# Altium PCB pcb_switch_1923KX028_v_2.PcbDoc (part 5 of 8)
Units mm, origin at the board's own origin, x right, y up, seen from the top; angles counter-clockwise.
Board outline 297.2 x 112.05 mm, 6 copper layers (Component Side, GND Layer 1, Inner Layer 1, Inner Layer 2, GND Layer 2, Solder Side), stack 1.578 mm thick; 545 components, 377 nets, 3174 pads, 1537 vias.
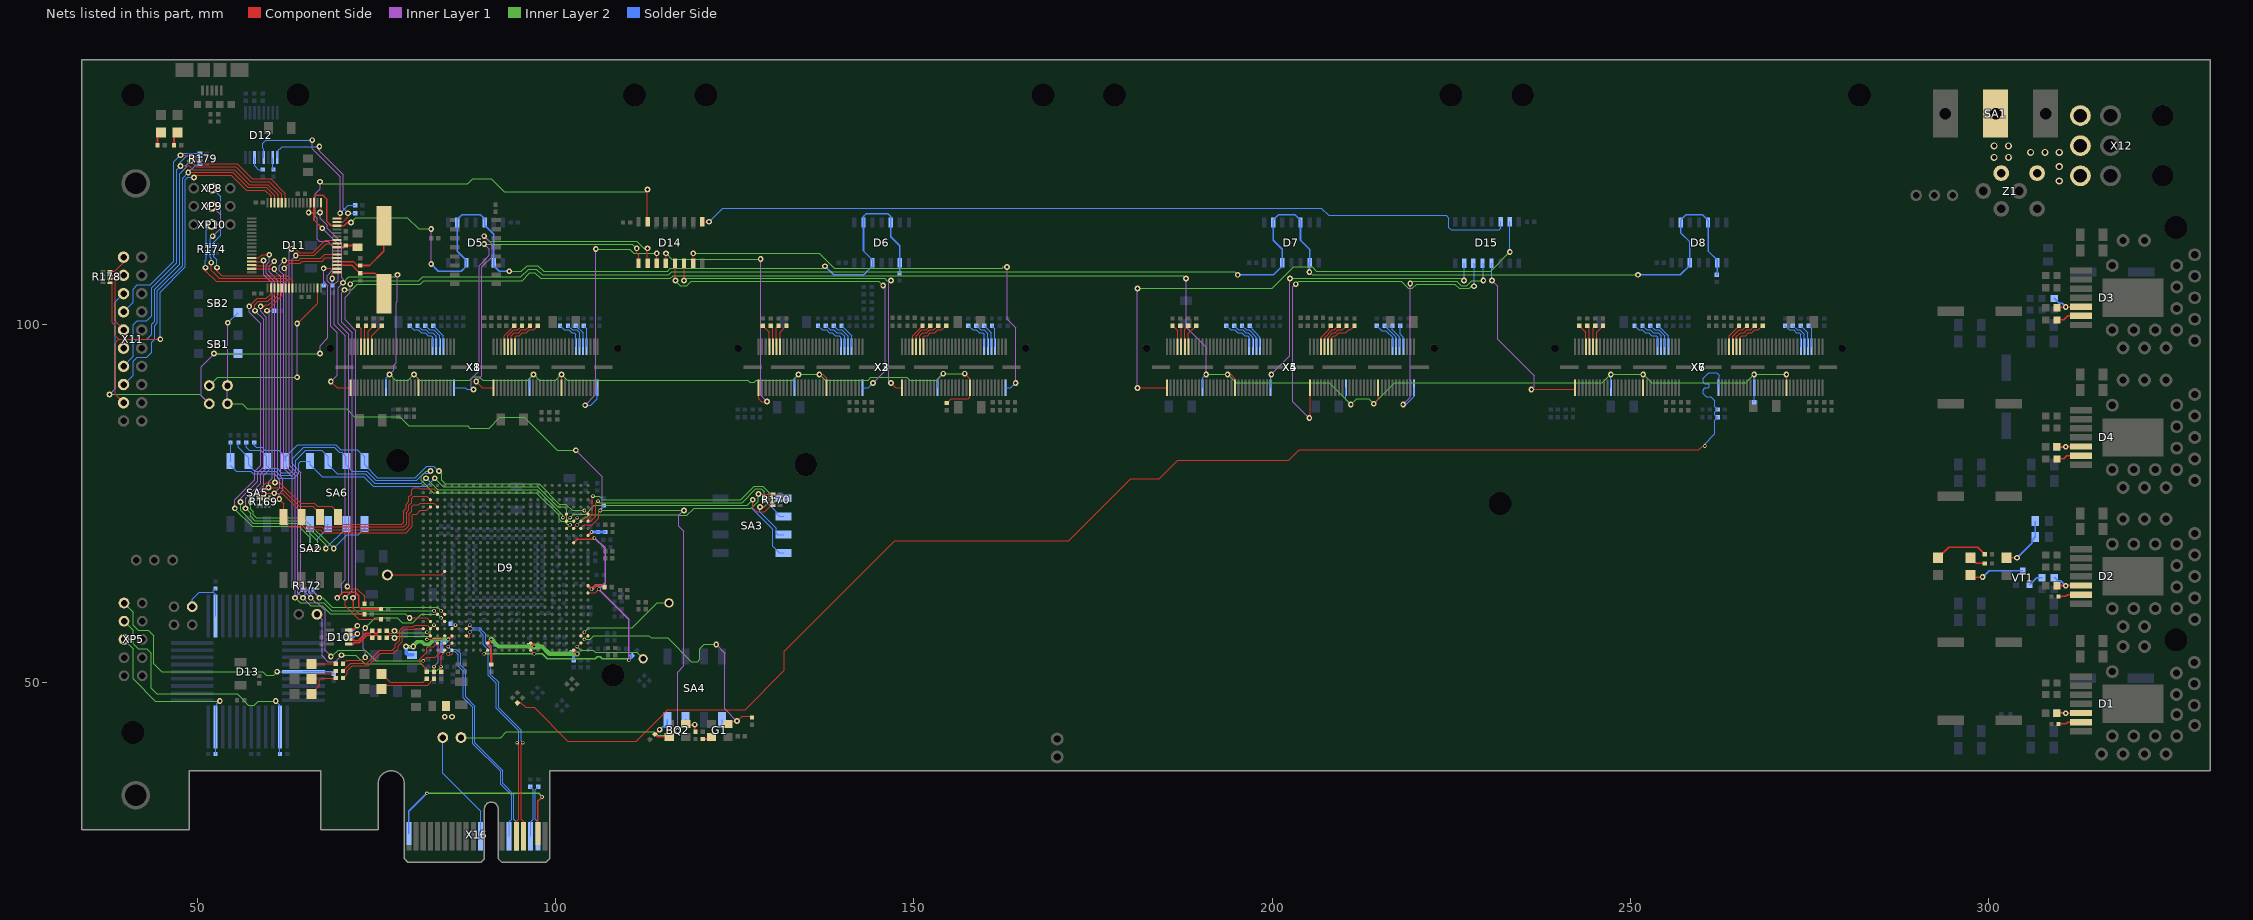
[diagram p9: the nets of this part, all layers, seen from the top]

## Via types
v1: diameter 0.8, hole 0.4, Component Side to Solder Side, tented both sides, 884 vias
v2: diameter 0.5, hole 0.3, Component Side to Solder Side, tented both sides, 269 vias
v3: diameter 1, hole 0.6, Component Side to Solder Side, tented both sides, 95 vias
v4: diameter 0.5/0.5/0.3/0.3/0.5/0.5 (per signal layer), hole 0.3, Component Side to Solder Side, tented both sides, 80 vias
v5: diameter 0.5/0.3/0.3/0.5/0.3/0.5 (per signal layer), hole 0.3, Component Side to Solder Side, tented both sides, 37 vias
v6: diameter 0.5/0.3/0.3/0.3/0.3/0.5 (per signal layer), hole 0.3, Component Side to Solder Side, tented both sides, 34 vias
v7: diameter 0.5/0.5/0.5/0.3/0.5/0.5 (per signal layer), hole 0.3, Component Side to Solder Side, tented both sides, 29 vias
v8: diameter 0.5, hole 0.3, Component Side to Solder Side, 25 vias
v9: diameter 0.5/0.3/0.5/0.3/0.3/0.5 (per signal layer), hole 0.3, Component Side to Solder Side, tented both sides, 25 vias
v10: diameter 0.5/0.5/0.3/0.5/0.5/0.5 (per signal layer), hole 0.3, Component Side to Solder Side, tented both sides, 19 vias
v11: diameter 0.6, hole 0.3, Component Side to Solder Side, tented both sides, 14 vias
v12: diameter 0.8, hole 0.5, Component Side to Solder Side, tented both sides, 11 vias
v13: diameter 0.5/0.3/0.5/0.5/0.3/0.5 (per signal layer), hole 0.3, Component Side to Solder Side, tented both sides, 7 vias
v14: diameter 0.8, hole 0.4, Component Side to Solder Side, 5 vias
v15: diameter 0.5/0.5/0.5/0.5/0.5/0.5 (per signal layer), hole 0.3, Component Side to Solder Side, tented both sides, 2 vias
v16: diameter 0.8, hole 0.5, Component Side to Solder Side, 1 vias

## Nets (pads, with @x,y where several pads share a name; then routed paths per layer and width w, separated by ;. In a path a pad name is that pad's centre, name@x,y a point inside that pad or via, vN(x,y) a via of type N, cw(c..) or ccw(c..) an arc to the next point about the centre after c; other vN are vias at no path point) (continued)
M_SGMII_L3DATI_3_P: C90.1 R93.2 R97.1 X7.59 | length 203.9
  Component Side w0.15: C90.1@94.654,47.146 95.134,47.146 95.781,46.5 96.962,46.5 101.672,41.79 111.228,41.79 115.638,46.2 126.438,46.2 131.91,51.672 131.91,54.372 147.338,69.8 171.638,69.8 180.238,78.4 184.238,78.4 186.838,81 202.338,81 203.819,82.481 259.6,82.481 260.119,83 v8(260.4,83)
  Solder Side w0.15: v8(260.4,83) 260.4,83.281 261.805,84.686 261.805,86.605 R97.1@262.2,87 261.805,87.395 261.805,87.705 R93.2@262.2,88.1 261.805,88.495 261.805,89.333 261.228,89.91 260.59,89.91 260.21,90.29 260.21,90.8 cw(c260.51,90.8) 260.51,91.1 260.732,91.1 ccw(c260.732,91.4) 261.032,91.4 ccw(c260.732,91.4) 260.732,91.7 260.51,91.7 cw(c260.51,92) 260.21,92 260.21,92.472 260.938,93.2 262.11,93.2 262.41,92.9 262.41,92.455 262.315,92.36 X7.59@262.315,91.135
MCU_A_3.3V: C118.2 D11.24 L4.2 | length 3.1
  Component Side w0.3: D11.24@69.45,110.75 70.45,110.75 C118.2@70.7,111 72.05,111 L4.2@72.3,110.75
MCU_FS: D11.4 SA6.6 | length 52.5
  Component Side w0.15: v1(58.8,102.5) 59.3,102.5 59.5,102.7 59.9,102.7 61.25,104.05 D11.4@61.25,105.05
  Inner Layer 1 w0.15: v1(56.7,74.3) 56.7,75.7 58.8,77.8 58.8,79.1 59.6,79.9 59.6,101 58.8,101.8 v1(58.8,102.5)
  Inner Layer 2 w0.15: v1(56.7,74.3) 57.4,73.6 57.4,73.2 58,72.6 64.5,72.6 67.9,69.2 v1(67.9,68.7)
  Solder Side w0.15: v1(67.9,68.7) 70.8,71.6 70.8,72 70.77,72.03 SA6.6@70.77,72.1
MCU_MISO: D11.5 R175.2 SA6.5 | length 54.2
  Component Side w0.15: v1(59.7,101.9) 61.75,103.95 D11.5@61.75,105.05
  Inner Layer 1 w0.15: v1(57.4,75.2) 57.4,75.7 59.2,77.5 59.2,78.9 60,79.7 60,101.6 v1(59.7,101.9)
  Inner Layer 2 w0.15: v1(57.4,75.2) 57.4,74.2 57.8,73.8 57.8,73.4 58.2,73 64.7,73 v1(69,68.7)
  Solder Side w0.15: v1(59.7,101.9) R175.2@60.7,101.9 ; v1(69,68.7) 70.9,70.6 72.4,70.6 73.4,71.6 73.4,72 73.31,72.09 SA6.5@73.31,72.1
MCU_MOSI: D11.2 SA6.8 | length 52.1
  Component Side w0.15: v1(57.2,102.5) 58.3,103.6 59.6,103.6 60.25,104.25 D11.2@60.25,105.05
  Inner Layer 1 w0.15: v1(55.2,74.3) 55.2,75.5 58,78.3 58,79.5 58.8,80.3 58.8,100.1 57.2,101.7 v1(57.2,102.5)
  Inner Layer 2 w0.15: v1(55.2,74.3) 55.2,74.2 57.6,71.8 64.1,71.8 65.7,70.2 v1(65.7,68.7)
  Solder Side w0.15: SA6.8@65.69,72.1 65.7,72.09 v1(65.7,68.7)
MCU_SCK: D11.3 SA6.7 | length 52.4
  Component Side w0.15: v1@57.9,101.9 58,102 58,102.7 58.5,103.2 59.8,103.2 60.75,104.15 D11.3@60.75,105.05
  Inner Layer 1 w0.15: v1(56,75.2) 56,75.7 58.4,78.1 58.4,79.3 59.2,80.1 59.2,100.7 v1(58,101.9)
  Inner Layer 2 w0.15: v1(56,75.2) 56,74 57.8,72.2 64.3,72.2 66.8,69.7 v1(66.8,68.7)
  Solder Side w0.15: v1(66.8,68.7) 66.8,70.1 68.2,71.5 68.2,72.1 SA6.7@68.23,72.1
MDC_1: D5.2 D5.5 D5.9 D5.12 D6.2 D6.5 D6.9 D6.12 D11.30 D11.35 R94.2 R225.2 | length 192.3
  Component Side w0.22: v1(67.4,113.4) 66.25,114.55 D11.35@66.25,116.95 66.25,117.75 66.5,118 67.5,118 68,117.5 68,114.4 68.65,113.75 D11.30@69.45,113.75 70.45,113.75 70.9,114.2 v1(71.4,114.2) ; v1(69.5,61.8) 70.3,62.6 72,62.6 72.5,62.1 72.5,60.6 72.85,60.25 R225.2@75.6,60.25
  Inner Layer 1 w0.17: v1(67.4,113.4) 69.6,111.2 69.6,106.1 69.1,105.6 69.1,99.9 70.6,98.4 70.6,64.3 70.1,63.8 70.1,62.4 v1(69.5,61.8) ; v1(82.6,108.4) v1(82.6,113.3)
  Inner Layer 2 w0.17: v1(71.4,114.2) 72.1,114.9 79.3,114.9 80.9,113.3 v1(82.6,113.3) ; v1(93.5,107.4) 95.2,107.4 96,108.2 97.5,108.2 98.3,107.4 115.6,107.4 116,107.8 137.3,107.8 v1(137.6,108.1)
  Solder Side w0.22: v1(82.6,108.4) 83.6,107.4 86.8,107.4 87.53,108.13 D5.5@87.53,108.6 87.53,108.97 87.5,108.94 86.26,110.18 D5.9@86.26,114.2 86.26,114.66 86.9,115.3 89.5,115.3 90.07,114.73 D5.12@90.07,114.2 90.07,113.83 91.34,112.56 D5.2@91.34,108.6 91.34,108.16 92.1,107.4 v1(93.5,107.4) ; v1(137.6,108.1) 138.8,106.9 143,106.9 144.23,108.13 D6.12@144.23,108.6 144.23,108.97 142.96,110.24 D6.2@142.96,114.2 142.96,115.06 143.3,115.4 146.4,115.4 146.77,115.03 D6.5@146.77,114.2 146.77,112.23 148.04,110.96 D6.9@148.04,108.6 148.04,107.14 R94.2@148,107.1
MDC_2: D7.2 D7.5 D7.9 D7.12 D8.2 D8.5 D8.9 D8.12 R95.2 R226.2 | length 272.9
  Component Side w0.22: v1(71.7,61.8) 71.7,60.4 72.6,59.5 R226.2@73.3,59.5
  Inner Layer 1 w0.17: v1(71.3,105.6) 71.3,104.5 70.6,103.8 70.6,100.6 72.1,99.1 72.1,62.2 v1(71.7,61.8)
  Inner Layer 2 w0.17: v1(71.3,105.6) 71.8,106.1 80.9,106.1 81.4,106.6 95.1,106.6 96.2,107.7 97.3,107.7 98.1,106.9 115.8,106.9 116.2,107.3 194.8,107.3 v1(195.2,106.9) ; v1(205.2,107.3) 205.6,106.9 v1(251.1,106.9)
  Solder Side w0.22: v1(195.2,106.9) 200.2,106.9 201.43,108.13 D7.12@201.43,108.6 201.43,110.47 200.16,111.74 D7.2@200.16,114.2 200.16,114.56 200.9,115.3 203.2,115.3 203.97,114.53 D7.5@203.97,114.2 203.97,111.73 205.24,110.46 D7.9@205.24,108.6 205.2,108.56 v1(205.2,107.3) ; v1(251.1,106.9) 257,106.9 258.33,108.23 D8.12@258.33,108.6 258.33,111.47 257.06,112.74 D8.2@257.06,114.2 257.06,114.56 257.8,115.3 260.1,115.3 260.87,114.53 D8.5@260.87,114.2 260.87,110.23 262.14,108.96 D8.9@262.14,108.6 262.14,106.94 R95.2@262.1,106.9
MDIO_1: D11.33 D11.36 R100.2 R111.2 X1.39 X1.99 X2.39 X2.99 X3.39 X3.99 X8.39 X8.99 | length 192.4
  Component Side w0.15: v1(65.5,115.6) 65.75,115.85 D11.36@65.75,116.95 ; v1(67.1,115.6) 67.25,115.75 D11.33@67.25,116.95 ; v1(70.9,63.4) 71.2,63.1 72.2,63.1 73.3,62 R111.2@73.3,61 ; v1(80.2,93) 80.815,92.385 X1.39@80.815,91.135 ; v1(100.8,93) 100.82,92.98 X1.99@100.82,91.135 ; v1(136.8,93) 137.3,93 137.815,92.485 X2.39@137.815,91.135 ; R100.2@154.6,89 155.2,89.6 157.6,89.6 157.82,89.82 X2.99@157.82,91.135 157.82,92.38 v1(157.1,93.1)
  Inner Layer 1 w0.15: v1(67.1,115.6) 67.1,114.8 68.1,113.8 68.1,113.4 70.1,111.4 70.1,106.5 70.3,106.3 v1(70.3,105.8) 69.6,105.1 69.6,100.1 71.1,98.6 71.1,63.6 v1(70.9,63.4) ; v1(76.8,93) 77.4,93.6 77.4,94.3 77.7,94.6 77.7,103 77.9,103.2 v1(77.9,106.9)
  Inner Layer 2 w0.15: v1(65.5,115.6) v1(67.1,115.6) ; v1(70.3,105.8) 71.1,106.6 77.6,106.6 v1(77.9,106.9) ; v1(76.8,93) 77.6,92.2 79.4,92.2 v1(80.2,93) 81,92.2 88,92.2 88.5,92.7 89.3,92.7 89.8,92.2 96.1,92.2 v1(96.9,93) 97.7,92.2 100,92.2 v1(100.8,93) 101.6,92.2 126.8,92.2 127.1,91.9 127.7,91.9 128,92.2 133.1,92.2 v1(133.9,93) v1(136.8,93) 137.6,92.2 143.6,92.2 144,92.6 149,92.6 149.4,92.2 153.2,92.2 v1(154.1,93.1) v1(157.1,93.1)
  Solder Side w0.15: X8.99@76.31,91.135 76.31,92.51 v1(76.8,93) ; X8.39@96.315,91.135 96.315,92.415 v1(96.9,93) ; X3.99@133.31,91.135 133.31,92.41 v1(133.9,93) ; X3.39@153.315,91.135 153.315,92.415 154,93.1 v1(154.1,93.1)
MDIO_2: R104.2 R227.2 X4.39 X4.99 X5.39 X5.99 X6.39 X6.99 X7.39 X7.99 | length 290.1
  Component Side w0.15: v1(70.6,61.8) 70.6,60.7 72.5,58.8 R227.2@75.6,58.8 ; v1(193.8,93) 194.2,93 194.815,92.385 X4.39@194.815,91.135 ; v1(214.2,88.9) 214.82,89.52 X4.99@214.82,91.135 ; v1(251.8,93) 251.815,92.985 X6.39@251.815,91.135 ; v1(271.8,93) 271.82,92.98 X6.99@271.82,91.135
  Inner Layer 1 w0.15: v1(70.5,104.8) 70.1,104.4 70.1,100.3 71.6,98.8 71.6,62.8 v1(70.6,61.8) ; v1(188,106.4) 188,99.6 190.8,96.8 v1(190.8,93)
  Inner Layer 2 w0.15: v1(70.5,104.8) 71.5,104.8 72.3,105.6 81.1,105.6 81.6,106.1 95.3,106.1 96.4,107.2 97.1,107.2 97.9,106.4 116,106.4 116.4,106.8 187.6,106.8 v1(188,106.4) ; v1(190.8,93) v1(193.8,93) 195,91.8 208,91.8 v1(211,88.8) 211.8,89.6 213.5,89.6 v1(214.2,88.9) 217.1,91.8 246.1,91.8 v1(247.3,93) v1(251.8,93) 253,91.8 266.1,91.8 v1(267.3,93) v1(271.8,93)
  Solder Side w0.15: X5.99@190.31,91.135 190.31,92.51 v1(190.8,93) ; X5.39@210.315,91.135 210.315,89.485 v1(211,88.8) ; v1(247.3,93) 247.31,92.99 X7.99@247.31,91.135 ; R104.2@267.3,89.1 267.315,89.115 X7.39@267.315,91.135 267.315,92.985 v1(267.3,93)
NET_CLK_3VP: D9.AB23 X15.1 | length 14.2
  Component Side w0.15: D9.AB23@103.5,56.5 v10(104,57)
  Inner Layer 2 w0.17: v10(104,57) 104.6,57.6 110.7,57.6 114.2,61.1 X15.1@115.8,61.1
NET_DX_N: D9.AB2 R139.2 | length 6.7
  Component Side w0.15: R139.2@76.4,57.225 76.745,56.88 77.18,56.88 v1(77.5,57.2) ; v2(82,57) D9.AB2@82.5,56.5
  Inner Layer 2 w0.15: v1(77.5,57.2) 77.775,56.925 81.925,56.925 v2(82,57)
NET_DX_P: D9.AA3 R138.2 | length 8.8
  Component Side w0.15: R138.2@76.4,56.225 76.745,56.57 77.13,56.57 v1(77.5,56.2) ; v10(83,58) D9.AA3@83.5,57.5
  Inner Layer 2 w0.15: v1(77.5,56.2) 77.775,56.475 82.275,56.475 82.5,56.7 82.5,57.5 v10(83,58)
NET_FIL_3.3V: C211.1 C212.1 C217.1 C218.1 C219.1 C220.1 C224.1 C225.1 C226.1 D9.AC10 D9.AC16 D9.AD22 D9.H24 D9.R24 L5.2 | length 29.1
  Component Side w0.2: 90.9,55.1 91,55 91,54
  Component Side w0.3: 105.4,63.4 105.55,63.55 106.55,63.55 C218.1@106.8,63.3
  Component Side w0.4: 90.9,55.1 D9.AC10@90.5,55.5 v13(91,56) ; C220.1@91,52.5 91,54 ; D9.AC16@96.5,55.5 v10(97,55) ; D9.R24@104.5,63.5 v15(105,63) 105.4,63.4 ; D9.H24@104.5,70.5 v2(105,71)
  Component Side w0.5: D9.AD22@102.5,54.5 v15(103,54)
  Inner Layer 2 w0.6: 91.2,55.8 92,55 96.4,55 ; 97.612,55 98.1,55 99.1,54 102.6,54
  Inner Layer 2 w0.8: v13(91,56) 91.2,55.8 ; 96.4,55 v10(97,55) 97.612,55 ; 102.6,54 v15(103,54)
  Solder Side w0.3: 105.4,63.4 105.55,63.55 106.8,63.55 C226.1@106.8,63.4
  Solder Side w0.4: v13(91,56) 91.6,55.4 C225.1@91.6,55.3 ; C219.1@96.3,55.2 96.8,55.2 v10(97,55) ; C211.1@102.2,54.2 102.3,54.2 102.5,54 ; C212.1@102.5,53.2 102.5,54 ; v15(103,54) 102.5,54 ; v15(105,63) 105.4,63.4 ; v2(105,71) C224.1@106.8,71
  other v1: 84.5,45.2 85.5,45.2
NET_FREQ_0_F21: D9.F21 R170.5 SA3.8 | length 41.3
  Component Side w0.15: D9.F21@101.5,72.5 v13(102,73) ; v1(127.5,75.5) 127.5,74.4 128.1,73.8 129.2,73.8 130.1,74.7 R170.5@130.3,74.7
  Inner Layer 2 w0.15: v13(102,73) 102.5,73.5 104.2,73.5 105.4,74.7 126.7,74.7 v1(127.5,75.5)
  Solder Side w0.15: v1(127.5,75.5) 127.5,74.2 130.3,71.4 130.3,69 131.21,68.09 SA3.8@131.8,68.09
NET_FREQ_1_F23: D9.F23 R170.6 SA3.7 | length 41.3
  Component Side w0.15: D9.F23@103.5,72.5 104,73 104.7,73 105.1,73.4 105.1,75.9 v2(105.2,76) ; v1(128.5,74.5) 129.1,74.5 129.85,75.25 R170.6@130.3,75.25
  Inner Layer 2 w0.15: v2(105.2,76) 106.1,76 106.6,75.5 125.8,75.5 127.7,77.4 128.9,77.4 129.8,76.5 129.8,75.2 129.1,74.5 v1(128.5,74.5)
  Solder Side w0.15: v1(128.5,74.5) 128.5,73.8 130.8,71.5 130.8,70.8 130.97,70.63 SA3.7@131.8,70.63
NET_FREQ_2_F24: D9.F24 R170.7 SA3.6 | length 34
  Component Side w0.15: D9.F24@104.5,72.5 104.9,72.5 105.6,73.2 105.6,75 v2(105.9,75.3) ; v1(129.1,75.5) 129.35,75.75 R170.7@130.3,75.75
  Inner Layer 2 w0.15: v2(105.9,75.3) 106.1,75.1 126,75.1 127.9,77 128.7,77 129.1,76.6 v1(129.1,75.5)
  Solder Side w0.15: v1(129.1,75.5) 130.8,73.8 130.8,73.6 131.23,73.17 SA3.6@131.8,73.17
NET_FREQ_3_G22: D9.G22 R170.8 SA3.5 | length 34.2
  Component Side w0.15: D9.G22@102.5,71.5 v13(103,72) ; v1(128.3,76.3) R170.8@130.3,76.3
  Inner Layer 2 w0.15: v13(103,72) 104.1,73.1 104.4,73.1 104.7,73.4 117.2,73.4 117.3,73.3 118.3,73.3 119.3,74.3 127.3,74.3 128.3,75.3 v1(128.3,76.3)
  Solder Side w0.15: v1(128.3,76.3) 130.6,76.3 131.19,75.71 SA3.5@131.8,75.71
NET_MCU_JA_TCK: D11.45 R179.3 X11.9 | length 49.6
  Component Side w0.15: v1(47.6,122.1) 48.8,122.1 49.3,121.6 55.1,121.6 57.2,119.5 59.8,119.5 61.25,118.05 D11.45@61.25,116.95
  Solder Side w0.15: X11.9@39.66,96.66 41,98 41,99.9 41.6,100.5 42.9,100.5 43.6,101.2 43.6,105.1 47.1,108.6 47.1,121.6 v1(47.6,122.1) 47.6,122.6 48.5,123.5 49.5,123.5 49.65,123.35 R179.3@50.3,123.35
NET_MCU_JA_TDI: D11.46 R179.1 X11.5 | length 50.7
  Component Side w0.15: v1@48.7,121 48.9,121.2 54.9,121.2 57,119.1 59.6,119.1 60.75,117.95 D11.46@60.75,116.95
  Solder Side w0.15: X11.5@39.66,91.58 39.68,91.58 41,92.9 41,94.8 41.6,95.4 42.9,95.4 43.6,96.1 43.6,97.5 44,97.9 44,99.8 44.4,100.2 44.4,104.7 47.9,108.2 47.9,120.4 v1(48.7,121.2) 49.8,122.3 R179.1@50.3,122.3
NET_MCU_JA_TDO: D11.43 R179.4 X11.13 | length 47.2
  Component Side w0.15: v1(47.6,123.6) 49.2,123.6 50.4,122.4 50.5,122.4 55.5,122.4 57.6,120.3 60.2,120.3 62.25,118.25 D11.43@62.25,116.95
  Solder Side w0.15: X11.13@39.66,101.74 39.66,101.76 41,103.1 41,104.9 41.6,105.5 43.4,105.5 46.7,108.8 46.7,122.7 v1(47.6,123.6) 47.9,123.9 R179.4@50.3,123.9
NET_MCU_JA_TMS: D11.44 R179.2 X11.7 | length 50.5
  Component Side w0.15: v1(49,122.8) 49.8,122 55.3,122 57.4,119.9 60,119.9 61.75,118.15 D11.44@61.75,116.95
  Solder Side w0.15: X11.7@39.66,94.12 39.66,94.16 41,95.5 41,97.3 41.6,97.9 42.9,97.9 43.6,98.6 43.6,100 44,100.4 44,104.9 47.5,108.4 47.5,121 48.4,121.9 48.4,122.2 v1(49,122.8) 49.6,122.8 49.65,122.85 R179.2@50.3,122.85
NET_MCU_JA_TRST: D11.47 R178.8 X11.3 | length 62.1
  Component Side w0.15: R178.8@37.8,105.8 38,105.8 38.1,105.7 38.1,100.2 38.5,99.8 38.5,98.4 39,97.9 ; X11.3@39.66,89.04 38.5,90.2 38.5,97.4 39,97.9 ; v1(44.8,97.9) 39,97.9 ; v1(49.5,120.5) 49.8,120.8 54.7,120.8 56.8,118.7 59.4,118.7 60.25,117.85 D11.47@60.25,116.95
  Solder Side w0.15: X11.3@39.66,89.04 X11.3@39.66,89.16 ; v1(44.8,97.9) 44.8,104.5 48.3,108 48.3,120.2 48.6,120.5 v1(49.5,120.5)
NET_MCU_OSC_IN: BQ1.1 C116.2 D11.19 | length 9.2
  Component Side w0.22: D11.19@69.45,108.25 71.55,108.25 C116.2@72.7,107.1 74.5,107.1 74.8,107.1 76,105.9 BQ1.1@76,104.25
NET_MCU_OSC_OUT: BQ1.2 C117.2 D11.20 | length 11.2
  Component Side w0.22: D11.20@69.45,108.75 71.75,108.75 72.3,108.2 C117.2@72.7,108.2 73.3,108.2 74,108.2 76,110.2 BQ1.2@76,113.75
NET_MCU_RESET: D11.18 R171.2 SB1.1 X11.15 XP6.2 | length 72.6
  Component Side w0.15: v1(67.6,107.8) 68.5,107.8 68.55,107.75 D11.18@69.45,107.75
  Inner Layer 1 w0.15: XP6.2@51.63,88.9 50.5,90.03 50.5,94.1 v1(52.3,95.9) ; v1(67.1,95.9) 67.1,97 68.2,98.1 68.2,105.4 67.6,106 v1(67.6,107.8)
  Inner Layer 2 w0.15: v1(37.7,90.2) 50.33,90.2 XP6.2@51.63,88.9 ; v1(52.3,95.9) v1(67.1,95.9)
  Solder Side w0.15: v1(37.7,90.2) 38.5,91 38.5,103.12 X11.15@39.66,104.28 ; v1(52.3,95.9) 55.62,95.9 SB1.1@55.65,95.93 ; R171.2@67.6,105.4 v1(67.6,107.8)
NET_MCU_U2_RX: D11.31 D12.1 R6.2 | length 21.3
  Component Side w0.15: D11.31@69.45,114.25 70.25,114.25 71,115 v1(71,115.5)
  Inner Layer 1 w0.15: v1(67,124.8) 67,124.2 70.3,120.9 70.3,116.2 v1(71,115.5)
  Solder Side w0.15: D12.1@61.122,123.276 61.122,124.122 61.8,124.8 66.952,124.8 66.976,124.776 v1(67,124.8) ; v1(71,115.5) R6.2@72,115.5
NET_MCU_U2_TX: D11.32 D12.4 R152.2 | length 24.7
  Component Side w0.15: D11.32@69.45,114.75 69.9,114.75 v1(69.9,115.5)
  Inner Layer 1 w0.15: v1(66,125.7) 66,124.5 69.9,120.6 v1(69.9,115.5)
  Solder Side w0.15: D12.4@59.217,123.276 59.217,124.482 59.1,124.6 59.1,125.3 59.5,125.7 v1(66,125.7) ; v1(69.9,115.5) 71,116.6 R152.2@72,116.6
NET_MODE_0_D2: D9.D2 D11.63 R169.8 SA2.8 | length 64.4
  Component Side w0.15: D11.63@57.55,107.75 60.65,107.75 v1(60.7,107.7) ; R169.8@60,75.725 60.125,75.6 v1(61.4,75.6) 62.045,74.955 62.045,73.155 SA2.8@61.99,73.1 61.99,72.51 62.8,71.7 64.8,71.7 65.2,71.3 67.1,71.3 67.5,70.9 79.1,70.9 79.9,71.7 79.9,73.3 80.1,73.5 80.6,73.5 81.1,74 82,74 D9.D2@82.5,74.5
  Inner Layer 1 w0.15: v1(60.7,107.7) 60.7,107.5 61.6,106.6 61.6,78.7 61.9,78.4 61.9,76.8 61.4,76.3 v1(61.4,75.6)
NET_MODE_1_D3: D9.D3 D11.62 R169.7 SA2.7 | length 67.4
  Component Side w0.15: D11.62@57.55,108.25 57.6,108.2 60.1,108.2 v1(60.7,108.8) ; R169.7@59.45,75.725 59.45,76.15 59.7,76.4 v1(60.7,76.4) 61.8,76.4 64.53,73.67 SA2.7@64.53,73.1 64.53,72.57 65.4,71.7 67.3,71.7 67.7,71.3 78.9,71.3 79.5,71.9 79.5,73.5 79.9,73.9 79.9,74.5 80.2,74.8 80.9,74.8 81.1,75 83,75 D9.D3@83.5,74.5
  Inner Layer 1 w0.15: v1(60.7,76.4) 61.5,77.2 61.5,78.2 61.2,78.5 61.2,106.1 60,107.3 60,108.1 v1(60.7,108.8)
NET_MODE_2_C2: D9.C2 D11.61 R169.6 SA2.6 | length 65.2
  Component Side w0.15: D11.61@57.55,108.75 59.05,108.75 v1(59.2,108.9) ; R169.6@58.95,75.725 58.95,76.25 v1(59.9,77.2) 61.6,77.2 64.2,74.6 66.1,74.6 67.07,73.63 SA2.6@67.07,73.1 67.07,72.53 67.9,71.7 69.8,71.7 ; 69.7,71.7 78.7,71.7 79.1,72.1 79.1,73.7 79.5,74.1 79.5,74.7 79.9,75.1 79.9,75.7 80.2,76 82,76 D9.C2@82.5,75.5
  Inner Layer 1 w0.15: v1(59.2,108.9) 59.2,106.9 60.4,105.7 60.4,78.5 59.9,78 v1(59.9,77.2)
NET_MODE_3_B3: D9.B3 D11.60 R169.5 SA2.5 | length 69.2
  Component Side w0.15: D11.60@57.55,109.25 58.55,109.25 59,109.7 v1(60,109.7) ; R169.5@58.4,75.725 58.4,76.3 59.2,77.1 59.2,77.5 59.6,77.9 v1(60.8,77.9) 61.5,77.9 64.4,75 66.3,75 66.7,74.6 68.7,74.6 69.61,73.69 SA2.5@69.61,73.1 69.61,72.39 69.9,72.1 78.5,72.1 78.7,72.3 78.7,73.9 79.1,74.3 79.1,74.9 79.5,75.3 79.5,75.9 79.9,76.3 79.9,76.9 80.2,77.2 80.9,77.2 81.1,77 83,77 D9.B3@83.5,76.5
  Inner Layer 1 w0.15: v1(60,109.7) 60,108.7 59.6,108.3 59.6,107.1 60.8,105.9 v1(60.8,77.9)
NET_NTRST_AD4: D9.AD4 R144.1 XP11.2 | length 27.8
  Component Side w0.15: R144.1@84,51.5 v10(84,52.2) 84,53.7 84.5,54.2 D9.AD4@84.5,54.5
  Inner Layer 1 w0.15: XP11.2@66.67,59.5 67.4,58.77 67.4,53.7 68.2,52.9 69.2,52.9 v1(70.1,53.8)
  Inner Layer 2 w0.15: v1(70.1,53.8) 72.1,53.8 73.3,52.6 81.2,52.6 82.2,51.6 83.4,51.6 v10(84,52.2)
NET_OSC_BYP_AB24: D9.AB24 G1.1 R180.2 SA4.5 | length 41
  Component Side w0.15: v10(104,56) D9.AB24@104.5,56.5 ; G1.1@124.1,44.3 124.05,44.25 G1.1@124.05,44.2 124.45,44.6 v1(125.3,44.6) 126,45.3 127.2,45.3 R180.2@127.4,45.1
  Inner Layer 1 w0.15: v1(122.4,55.3) 123.6,54.1 123.6,46.3 v1(125.3,44.6)
  Inner Layer 2 w0.15: v10(104,56) 104.8,56 105.3,56.5 113,56.5 113.3,56.2 115.6,56.2 118.9,52.9 119.8,52.9 120.1,53.2 120.1,54.7 120.7,55.3 v1(122.4,55.3)
  Solder Side w0.15: SA4.5@123.11,44.3 SA4.5@123.21,44.3 ; SA4.5@123.21,44.8 123.21,44.6 v1(125.3,44.6)
NET_PLLOUT: D9.AC23 X14.1 | length 10.6
  Component Side w0.15: v10(103,55) D9.AC23@103.5,55.5
  Inner Layer 2 w0.15: v10(103,55) 103.5,54.5 105.2,54.5 105.5,54.2 111.3,54.2 X14.1@112.2,53.3
NET_RDLH: D9.AC3 R162.1 | length 5.9
  Component Side w0.15: R162.1@82,51.5 81.8,51.7 81.8,52 81,52.8 81,53.2 82,54.2 82,54.8 82.2,55 83,55 D9.AC3@83.5,55.5
NET_RESET_G23: D9.G23 R181.2 SB2.1 XP2.2 XP6.1 XP7.1 | length 155.9
  Component Side w0.15: D9.G23@103.5,71.5 104,72 105.1,72 106,72.9 106,73.8 v2(106.2,74)
  Inner Layer 1 w0.15: XP6.1@54.17,88.9 XP7.1@54.17,91.44 54.2,91.47 v1(54.2,100.2) ; v1(102.8,82.4) 106.5,78.7 106.5,74.3 v2(106.2,74) ; v1@117.2,43.5 v1(117,43.3) 117,51.4 117.9,52.3 117.9,71.122 117.2,71.822 117.2,73.3 v1(117.9,74)
  Inner Layer 2 w0.15: XP6.1@54.17,88.9 56.2,88.9 56.9,88.2 70.8,88.2 71.9,87.1 78.2,87.1 79.5,85.8 87.7,85.8 88,85.5 90.7,85.5 92.2,87 95.6,87 100.2,82.4 v1(102.8,82.4) ; XP2.2@86.77,42.3 92.3,42.3 93.1,43.1 113.6,43.1 114.1,42.6 116.3,42.6 v1(117,43.3) ; v2(106.2,74) v1(117.9,74)
  Solder Side w0.15: v1(54.2,100.2) 54.22,100.2 SB2.1@55.65,101.63 ; v2(106.2,74) 106.2,74.1 R181.2@106.8,74.7
NET_SMLH: D9.AB4 R163.1 | length 8.6
  Component Side w0.15: v2(82,56) 84,56 D9.AB4@84.5,56.5 ; R163.1@83,51.5 v2(83,52.2)
  Inner Layer 1 w0.15: v2(82,56) 82.9,56 83.6,55.3 83.6,52.8 v2(83,52.2)
NET_SPEED_MD_0_Y4: D9.Y4 R140.1 | length 20.7
  Component Side w0.15: R140.1@70.3,52.6 70.8,53.1 73,53.1 v1(73.4,53.5) ; v10(84,59) D9.Y4@84.5,58.5
  Inner Layer 1 w0.15: v1(73.4,53.5) 73.4,54.4 73.1,54.7 73.1,57.3 v1(73.4,57.6)
  Inner Layer 2 w0.15: v1(73.4,57.6) 74.8,59 77.9,59 78.6,58.3 80,58.3 81.2,59.5 83.5,59.5 v10(84,59)
NET_SPEED_MD_1_AA2: D9.AA2 R143.1 | length 16.1
  Component Side w0.15: R143.1@70.3,51.6 71.4,52.7 73.6,52.7 75.4,54.5 77.2,54.5 77.6,54.9 77.6,55.3 78.2,55.9 78.2,57.3 78.7,57.8 80.1,57.8 80.3,58 82,58 82.1,57.9 D9.AA2@82.5,57.5
NET_SPEED_MD_2_AA1: D9.AA1 R145.1 | length 15.3
  Component Side w0.15: R145.1@70.3,50.6 70.9,51.2 70.9,51.6 71.6,52.3 73.8,52.3 75.6,54.1 77.4,54.1 78,54.7 78,55.1 78.6,55.7 78.6,57.1 78.9,57.4 80.3,57.4 80.4,57.5 D9.AA1@81.5,57.5
NET_SPI_NCS_G21: D9.G21 R161.1 SA5.3 SA6.3 | length 60.7
  Component Side w0.15: D9.G21@101.5,71.5 v13(102,72)
  Inner Layer 2 w0.15: v1(82.5,79.5) 81.9,79.5 81.2,78.8 81.2,78.2 82.9,76.5 97.3,76.5 100.5,73.3 100.5,72.8 100.8,72.5 101.2,72.5 101.7,72 v13(102,72)
  Solder Side w0.15: R161.1@56.8,83.5 56.8,82.8 57.2,82.4 58.8,82.4 59.67,81.53 SA5.3@59.67,80.9 59.67,80.23 60,79.9 61.1,79.9 61.7,79.3 63,79.3 63.3,79.6 63.3,81.3 64.8,82.8 69.1,82.8 69.8,82.1 70.1,82.1 70.77,81.43 SA6.3@70.77,80.9 70.77,80.33 71.6,79.5 73.6,79.5 74.9,78.2 80.6,78.2 81.6,79.2 82.2,79.2 v1(82.5,79.5)
NET_SPI_SCK_E21: D9.E21 R167.1 SA5.2 SA6.2 | length 56.6
  Component Side w0.15: v13(101,73) D9.E21@101.5,73.5
  Inner Layer 2 w0.15: v1(81.9,78.5) 83.5,76.9 97.4,76.9 101,73.3 v13(101,73)
  Solder Side w0.15: R167.1@55.7,83.5 55.7,82.8 57.13,81.37 SA5.2@57.13,80.9 57.13,80.37 58,79.5 60.9,79.5 61.5,78.9 63.2,78.9 63.7,79.4 63.7,81 65.1,82.4 67.3,82.4 68.23,81.47 SA6.2@68.23,80.9 68.23,80.37 69.5,79.1 73.4,79.1 74.7,77.8 81.2,77.8 v1(81.9,78.5)
NET_SPI_SI_F22: D9.F22 R164.1 SA5.1 SA6.1 | length 60.1
  Component Side w0.15: D9.F22@102.5,72.5 v13(103,73)
  Inner Layer 2 w0.15: v1(83.1,78.5) 84.3,77.3 97.5,77.3 100.3,74.5 101.2,74.5 101.5,74.2 101.5,72.7 101.7,72.5 102.5,72.5 v13(103,73)
  Solder Side w0.15: SA5.1@54.59,80.31 55.4,79.5 57.4,79.5 57.8,79.1 60.7,79.1 61.3,78.5 63.4,78.5 64.1,79.2 64.1,80.6 64.4,80.9 SA6.1@65.69,80.9 65.69,80.41 67.4,78.7 73.2,78.7 74.5,77.4 82,77.4 v1(83.1,78.5) ; SA5.1@54.59,80.9 54.6,80.9 R164.1@54.6,83.5
NET_SPI_SO_E24: D9.E24 R165.1 SA5.4 SA6.4 | length 55.5
  Component Side w0.15: v2(104,74) D9.E24@104.5,73.5
  Inner Layer 2 w0.15: v1(83.7,79.5) 84.1,79.1 84.1,78.2 84.6,77.7 97.7,77.7 100.5,74.9 101.4,74.9 102.3,74 v2(104,74)
  Solder Side w0.15: R165.1@57.9,83.5 57.9,83.1 58.2,82.8 59,82.8 59.4,82.4 61.3,82.4 62.21,81.49 SA5.4@62.21,81.41 ; SA5.4@62.21,80.9 SA5.4@62.21,81.41 ; v1(83.7,79.5) 83,80.2 82,80.2 80.4,78.6 75.1,78.6 73.31,80.39 SA6.4@73.31,80.9 73.31,81.49 72.3,82.5 70,82.5 69.3,83.2 64,83.2 SA5.4@62.21,81.41
NET_SWITCH_RST: D11.15 XP7.2 | length 26.4
  Component Side w0.15: v1(63.9,100.1) 66.75,102.95 D11.15@66.75,105.05
  Inner Layer 1 w0.15: v1(63.9,92.6) v1(63.9,100.1)
  Inner Layer 2 w0.15: XP7.2@51.63,91.44 52.79,92.6 v1(63.9,92.6)
NET_TCK_Y2: D9.Y2 D11.22 R172.4 | length 77.8
  Component Side w0.15: v1(62.1,108.9) 64.1,108.9 64.4,109.2 67.2,109.2 67.75,109.75 D11.22@69.45,109.75 ; v1(79.6,59) 82,59 D9.Y2@82.5,58.5
  Inner Layer 1 w0.15: v1(62.1,108.9) 61.4,108.2 61.4,107.5 62,106.9 62,79.9 63.2,78.7 63.2,63.2 63.6,62.8 v1(63.6,61.8)
  Inner Layer 2 w0.15: v1(63.6,61.8) 64.3,61.1 65.4,61.1 65.8,60.7 67.4,60.7 68.5,59.6 79,59.6 v1(79.6,59)
  Solder Side w0.15: v1(63.6,61.8) 63.6,61.9 64.5,62.8 R172.4@64.5,63
NET_TDI_W3: D9.W3 D11.26 R172.2 | length 77.3
  Component Side w0.15: v1(63.1,110.5) 63.7,110.5 64.2,110 66.1,110 67.85,111.75 D11.26@69.45,111.75 ; v10(83,60) D9.W3@83.5,59.5
  Inner Layer 1 w0.15: v1(63.1,110.5) 62.8,110.2 62.8,80.3 64,79.1 64,63.6 v1(65.8,61.8)
  Inner Layer 2 w0.15: v1(65.8,61.8) 66.5,61.1 67.6,61.1 68.7,60 v10(83,60)
  Solder Side w0.15: R172.2@65.55,63 65.55,62.55 65.8,62.3 v1(65.8,61.8)
NET_TDO_W4: D9.W4 D11.25 R172.1 | length 76.4
  Component Side w0.15: v1(63.7,109.6) 66.3,109.6 67.95,111.25 D11.25@69.45,111.25 ; v10(84,60) D9.W4@84.5,59.5
  Inner Layer 1 w0.15: v1(63.7,109.6) 63.2,109.1 63.2,80.5 64.4,79.3 64.4,63.8 65.7,62.5 66.3,62.5 v1(67,61.8)
  Inner Layer 2 w0.15: v1(67,61.8) 67.5,61.8 68.8,60.5 83.5,60.5 v10(84,60)
  Solder Side w0.15: R172.1@66.1,63 66.1,62.8 67,61.9 v1(67,61.8)
NET_TMP_DX_N: C120.2 D10.2 R139.1 | length 5.2
  Component Side w0.18: D10.2@71.1,56 71.74,56 71.895,55.845 72.409,55.845 73.459,56.895 74.07,56.895 C120.2@74.4,57.225 74.73,56.895 75.07,56.895 R139.1@75.4,57.225
NET_TMP_DX_P: C120.1 D10.1 R138.1 | length 5.2
  Component Side w0.18: D10.1@71.1,55.35 71.74,55.35 71.895,55.505 72.55,55.505 73.6,56.555 74.07,56.555 C120.1@74.4,56.225 74.73,56.555 75.07,56.555 R138.1@75.4,56.225
NET_TMS_AC4: D9.AC4 D11.21 R172.3 | length 85.1
  Component Side w0.15: v1(62.1,107.8) 62.8,108.5 64.3,108.5 64.6,108.8 67.4,108.8 67.85,109.25 D11.21@69.45,109.25 ; v2(81.5,53) 82,53.5 83.2,53.5 84,54.3 84,55 D9.AC4@84.5,55.5
  Inner Layer 1 w0.15: v1(62.1,107.8) 62.4,107.5 62.4,80.1 63.6,78.9 63.6,63.4 64,63 64,62.5 v1(64.7,61.8) 65.4,61.1 66.7,61.1 67.8,60 67.8,54.5 v1@68.6,53.7
  Inner Layer 2 w0.15: v1@68.6,53.7 68.8,53.7 69.6,54.5 73.4,54.5 74.9,53 v2(81.5,53)
  Solder Side w0.15: v1(64.7,61.8) 65.05,62.15 R172.3@65.05,63
  other v1: 68.6,53.6
NetC3_1: C3.1 D1.6 | length 3.2
  Component Side w0.2: C3.1@309.8,44.2 310.8,44.2 311.06,44.46 D1.6@312.92,44.46
NetC9_1: C9.1 D2.6 | length 3.2
  Component Side w0.2: C9.1@309.8,62 310.8,62 311.06,62.26 D2.6@312.92,62.26
NetC14_1: C14.1 D3.6 | length 3.7
  Component Side w0.2: C14.1@309.6,100.7 309.7,100.6 310.5,100.6 311.06,101.16 D3.6@312.92,101.16 D3.6@312.86,101.1
NetC78_1: C78.1 D4.6 | length 3.6
  Component Side w0.2: C78.1@309.6,81.4 309.8,81.2 310.5,81.2 310.96,81.66 D4.6@312.92,81.66
NetC202_1: C202.1 C203.1 D9.AB5 L1.2 | length 12.2
  Component Side w0.4: v10(85,56) D9.AB5@85.5,56.5
  Inner Layer 2 w0.5: v1(79.1,55) 80,55 80.7,55.7 81.3,55.7 81.7,55.3 82.3,55.3 83,56 v10(85,56)
  Solder Side w0.5: L1.2@80,53.85 79.35,53.85 79.1,54.1 v1(79.1,55) v1@80,55 ; C202.1@84.1,54.5 84.1,55.4 C203.1@84.2,55.5 84.5,55.5 v10(85,56)
  other v1: 80.1,55
NetD1_5: D1.5 R41.1 R44.1 | length 4.2
  Component Side w0.25: R44.1@310,45.7 311,45.7 312.89,45.7 D1.5@312.92,45.73
  Solder Side w0.25: R41.1@309.5,45.7 v1(310.8,45.7)
NetD2_5: D2.5 R47.1 R50.1 | length 5.4
  Component Side w0.25: R50.1@309.6,63.5 309.63,63.53 D2.5@312.92,63.53 D2.5@312.89,63.5
  Solder Side w0.25: R47.1@309.2,64.6 309.3,64.6 309.7,64.2 310.1,64.2 v1(310.8,63.5)
NetD3_5: D3.5 R53.1 R54.1 | length 5.4
  Component Side w0.2: R54.1@309.6,102.4 v1(310.8,102.4) 312.89,102.4 D3.5@312.92,102.43
  Solder Side w0.2: R53.1@309.2,103.6 309.9,102.9 310.3,102.9 v1(310.8,102.4)
NetD4_5: D4.5 R57.1 R58.1 | length 5
  Component Side w0.2: R58.1@309.6,83.1 309.8,82.9 v1(310.8,82.9) 312.89,82.9 D4.5@312.92,82.93 312.95,82.9 D4.5@313.15,83.1
  Solder Side w0.2: R57.1@309.5,82.9 v1(310.8,82.9)
NetD9_AA5: D9.AA5 R168.1 | length 1.5
  Component Side w0.15: D9.AA5@85.5,57.5 v7(86,58)
  Solder Side w0.15: R168.1@85.3,58.2 85.8,58.2 v7(86,58)
NetD9_AD10: D9.AD10 D9.AD16 D9.J22 D9.T24 R166.1 | length 47.9
  Component Side w0.15: D9.T24@104.5,62.5 105.5,62.5 v2(106,63)
  Component Side w0.2: v10(90,54) D9.AD10@90.5,54.5 ; D9.AD16@96.5,54.5 v10(97,54) ; D9.J22@102.5,69.5 103,70 105.2,70 v2(105.4,70.2)
  Inner Layer 1 w0.2: v2(105.4,70.2) 106.9,68.7 106.9,63.9 v2(106,63) 110.2,58.8 v2(110.2,53.1)
  Inner Layer 2 w0.2: v10(90,54) 98.1,54 98.8,53.3 105.5,53.3 105.8,53.6 106.2,53.6 106.5,53.3 110,53.3 v2(110.2,53.1)
  Solder Side w0.3: v2(110.2,53.1) 110.546,53.446 R166.1@110.546,53.846
NetD9_N4: D9.N4 X13.1 | length 8.2
  Component Side w0.15: X13.1@76.5,65 84,65 D9.N4@84.5,65.5
NetD10_3: D10.3 R109.1 | length 2.5
  Component Side w0.2: D10.3@71.1,56.65 72.15,56.65 v1(72.3,56.8)
  Solder Side w0.2: R109.1@71.3,56.3 71.8,56.3 v1(72.3,56.8)
NetD10_4: D10.4 R110.1 | length 2.7
  Component Side w0.2: D10.4@71.1,57.3 71.2,57.4 71.8,57.4 v1(72.3,57.9)
  Solder Side w0.2: R110.1@71.3,57.3 71.7,57.3 v1(72.3,57.9)
NetD11_6: D11.6 R174.5 | length 15.2
  Component Side w0.15: v1(51.1,107.9) 51.1,107.5 52.6,106 62.1,106 62.25,105.85 D11.6@62.25,105.05
  Solder Side w0.15: v1(51.1,107.9) 51.1,108.9 51.2,109 R174.5@51.2,110
NetD11_7: D11.7 R174.6 | length 15
  Component Side w0.15: v1(51.9,108.6) 51.9,107.5 52.1,107.3 53,106.4 62.3,106.4 62.75,105.95 D11.7@62.75,105.05
  Solder Side w0.15: R174.6@51.75,110 51.75,109.35 51.9,109.2 v1(51.9,108.6)
NetD11_8: D11.8 R174.7 | length 14.8
  Component Side w0.15: v1(52.7,107.9) 52.7,107.5 53.4,106.8 62.5,106.8 63.25,106.05 D11.8@63.25,105.05
  Solder Side w0.15: R174.7@52.25,110 52.25,109.45 52.7,109 v1(52.7,107.9)
NetD11_17: D11.17 R173.2 | length 2.5
  Component Side w0.15: v1(68.8,106.4) 68.8,107.1 68.95,107.25 D11.17@69.45,107.25 D11.17@69.5,107.2
  Solder Side w0.15: R173.2@68.8,105.4 v1(68.8,106.4)
NetD12_2: D12.2 R9.1 | length 1.7
  Solder Side w0.15: D12.2@60.487,123.276 60.487,121.712 R9.1@60.6,121.6
NetD12_6: D12.6 R10.1 | length 2.5
  Solder Side w0.15: D12.6@57.947,123.276 57.947,122.153 58.5,121.6 R10.1@59.1,121.6
NetD13_5: D13.5 R135.1 XP5.5 | length 27.1
  Inner Layer 2 w0.15: XP5.5@39.73,56 39.73,55.97 41,54.7 41,50.5 44.1,47.4 v1(53.1,47.4)
  Solder Side w0.15: R135.1@52.5,40 D13.5@52.5,43.75 52.5,46.6 52.7,46.8 52.7,47 v1(53.1,47.4)
NetD13_17: D13.17 R134.1 XP1.1 | length 8.5
  Solder Side w0.15: XP1.1@49.24,60.57 49.24,61.64 50.2,62.6 52.2,62.6 ; D13.17@52.5,59.25 52.5,62.3 52.2,62.6 ; R134.1@52.5,63.1 52.2,62.8 52.2,62.6
NetD13_32: D13.32 R136.1 XP5.9 | length 37
  Inner Layer 2 w0.15: XP5.9@39.73,61.08 39.73,61.07 41,59.8 41,58 41.7,57.3 43.1,57.3 43.9,56.5 43.9,52.6 45,51.5 59.1,51.5 59.6,51 60.6,51 v1(61.1,51.5)
  Solder Side w0.15: v1(61.1,51.5) D13.32@64.75,51.5
  Solder Side w0.2: D13.32@64.75,51.5 69,51.5
NetD13_38: D13.38 R137.1 XP5.7 | length 37.9
  Inner Layer 2 w0.15: XP5.7@39.73,58.54 39.76,58.54 41,57.3 41,55.4 41.7,54.7 42.9,54.7 43.5,54.1 43.5,49.2 44.3,48.4 55.5,48.4 57.1,46.8 57.9,46.8 58.5,47.4 v1(60.9,47.4)
  Solder Side w0.15: v1(60.9,47.4) 61.5,46.8 D13.38@61.5,43.75 R137.1@61.5,40
NetG1_3: G1.3 R102.2 | length 1.4
  Component Side w0.22: R102.2@120.5,42.1 121.45,42.1 G1.3@121.75,42.4
NetR11_1: R11.1 VD3.2 | length 2
  Component Side w0.22: R11.1@46.7,125 46.7,126.3 VD3.2@47.2,126.8
NetR12_1: R12.1 VD10.2 | length 2
  Component Side w0.22: R12.1@44.4,125 44.4,126.3 VD10.2@44.9,126.8
NetR30_2: R30.2 R34.2 VD1.1 | length 7.7
  Component Side w0.2: VD1.1@302.5,67.4 v1(304,67.4)
  Solder Side w0.2: v1(304,67.4) 306.1,69.5 306.1,69.85 R30.2@306.55,70.3 R34.2@306.55,72.5
NetR31_1: R31.1 VD2.1 | length 3
  Component Side w0.2: VD2.1@298,67.9 VD2.1@297.5,67.4 298.3,66.6 R31.1@299.5,66.6
NetR33_2: R33.2 VD4.1 | length 7.5
  Component Side w0.2: VD4.1@293,67.4 294.5,68.9 298.5,68.9 R33.2@299.5,67.9
NetR37_2: R37.2 VT1.1 | length 2.2
  Solder Side w0.2: VT1.1@305.75,63.6 306.75,64.6 R37.2@307.5,64.6
NetR140_2: R140.2 VD5.1 | length 3.4
  Component Side w0.15: VD5.1@65.9,52.6 R140.2@69.3,52.6
NetR143_2: R143.2 VD6.1 | length 3.9
  Component Side w0.15: VD6.1@65.9,50.5 66.6,51.2 68.9,51.2 R143.2@69.3,51.6
NetR145_2: R145.2 VD7.1 | length 4.8
  Component Side w0.15: VD7.1@65.9,48.4 67,49.5 67,50.3 67.3,50.6 R145.2@69.3,50.6
NetR162_2: R162.2 VD9.1 | length 7
  Component Side w0.15: VD9.1@75.7,51.2 76.9,50 81.5,50 R162.2@82,50.5
NetR163_2: R163.2 VD8.1 | length 7.9
  Component Side w0.15: VD8.1@75.7,49.1 76.2,49.6 82.1,49.6 R163.2@83,50.5
NetR174_1: R174.1 XP10.2 | length 3.3
  Solder Side w0.15: R174.1@51.2,111 51.2,113.12 XP10.2@52,113.92
NetR174_2: R174.2 XP9.2 | length 6.6
  Inner Layer 1 w0.15: XP9.2@52.04,116.46 53.2,115.3 53.2,113.4 v1(52.1,112.3)
  Inner Layer 2 w0.15: XP9.2@52,116.46 XP9.2@52.04,116.46
  Solder Side w0.15: R174.2@51.75,111 51.75,111.95 v1(52.1,112.3)
NetR174_3: R174.3 XP8.2 | length 9.4
  Solder Side w0.15: XP8.2@51.5,119 XP8.2@52,119 53.2,117.8 53.2,112.4 52.25,111.45 R174.3@52.25,111
NetR178_5: R178.5 X11.19 | length 3.1
  Component Side w0.15: R178.5@37.8,107.4 38.4,107.4 39.66,108.66 X11.19@39.66,109.36
NetR178_6: R178.6 X11.17 | length 1.9
  Component Side w0.15: R178.6@37.8,106.85 39.63,106.85 X11.17@39.66,106.82
NetR178_7: R178.7 X11.11 | length 8.2
  Component Side w0.15: R178.7@37.8,106.35 38.25,106.35 38.5,106.1 38.5,100.4 39.66,99.24 X11.11@39.66,99.2
NetSA1_2: SA1.2 Z1.1
  other v3: 300.8,123.3 302.8,123.3 300.8,124.9 302.8,124.9
NetVD2_2: VD2.2 VT1.3 | length 7.8
  Component Side w0.2: VD2.2@297.5,65 297.8,64.7 v1(299.2,64.7)
  Solder Side w0.2: v1(299.2,64.7) 300.1,65.6 VT1.3@304.8,65.6
NetX12_4: X12.4 X12.5 X12.6 Z1.3
  other v3: 309.9,120 309.9,122 305.9,124 307.9,124 309.9,124
NetX16_A1: X16.A1 X16.B17 | length 28.3
  Component Side w0.18: X16.B17@97.5,28.9 97.5,33.4 v2(98.1,34)
  Inner Layer 2 w0.18: v2(82,34.5) 97.6,34.5 v2(98.1,34)
  Solder Side w0.18: X16.A1@79.5,28.9 79.5,32 v2(82,34.5)
NetX16_A11: X16.A11 XP2.1 | length 16
  Solder Side w0.15: XP2.1@84.23,42.3 84.2,42.27 84.2,37.3 89.5,32 89.5,31 X16.A11@89.5,28.5
NEXT_REG: D14.9 D15.14 | length 115.6
  Component Side w0.15: D14.9@120.445,114.655 D14.9@120.445,114.3 v1(121.4,114.3)
  Solder Side w0.15: v1(121.4,114.3) 123.3,116.2 206.9,116.2 207.9,115.2 224.3,115.2 224.7,114.8 224.7,113.5 225,113.2 231.7,113.2 231.9,113.4 231.9,114.295 D15.14@231.905,114.3
OSC_XTAL1_IN: BQ2.1 C95.2 SA4.8 | length 5.4
  Component Side w0.22: v1(114.5,43.4) C95.2@113.854,42.754 114.207,42.4 BQ2.1@115.85,42.4
  Solder Side w0.15: SA4.8@115.4,44.3 SA4.8@115.49,44.3
  Solder Side w0.22: v1(114.5,43.4) 114.9,43.8 115.59,43.8 SA4.8@115.59,44.8
OSC_XTAL2_OUT: BQ2.3 C94.2 SA4.7 | length 4.8
  Component Side w0.22: BQ2.3@118.15,44.2 118.25,44.1 v1(119.4,44.1) 119.4,43.2 C94.2@119.5,43.1
  Solder Side w0.15: SA4.7@118.03,44.3 118.03,43.87 SA4.7@118.1,43.8
  Solder Side w0.22: SA4.7@118.13,44.8 118.13,44.1 v1(119.4,44.1)
P1_ADDR_0: R128.1 X1.8 | length 3.1
  Component Side w0.15: R128.1@72.4,99.8 72.815,99.385 X1.8@72.815,96.865
P1_ADDR_1: R129.1 X1.10 | length 3
  Component Side w0.15: X1.10@73.315,96.865 73.315,99.615 R129.1@73.5,99.8
P1_ADDR_2: R130.1 X1.12 | length 3.3
  Component Side w0.15: X1.12@73.815,96.865 73.815,99.015 R130.1@74.6,99.8
P1_ADDR_3: R132.1 X1.14 | length 3.5
  Component Side w0.15: X1.14@74.315,96.865 74.315,98.415 R132.1@75.7,99.8
P2_ADDR_0: R218.1 X8.68 | length 3.5
  Solder Side w0.15: R218.1@82.9,99.8 84.31,98.39 X8.68@84.31,96.865
P2_ADDR_1: R220.1 X8.70 | length 4.1
  Solder Side w0.15: R220.1@81.8,99.8 82.4,99.2 83,99.2 83.81,98.39 X8.70@83.81,96.865
P2_ADDR_2: R222.1 X8.72 | length 4.7
  Solder Side w0.15: R222.1@80.7,99.8 81.3,99.2 81.9,99.2 82.3,98.8 82.8,98.8 83.31,98.29 X8.72@83.31,96.865
P2_ADDR_3: R224.1 X8.74 | length 5.2
  Solder Side w0.15: R224.1@79.6,99.8 80.2,99.2 80.8,99.2 81.2,98.8 81.8,98.8 82.2,98.4 82.6,98.4 82.81,98.19 X8.74@82.81,96.865
P3_ADDR_0: R133.1 X1.68 | length 3.5
  Component Side w0.15: X1.68@92.82,96.865 92.82,98.42 R133.1@94.2,99.8
P3_ADDR_1: R147.1 X1.70 | length 4.1
  Component Side w0.15: X1.70@93.32,96.865 93.32,98.42 94.1,99.2 94.7,99.2 R147.1@95.3,99.8
P3_ADDR_2: R146.1 X1.72 | length 4.7
  Component Side w0.15: X1.72@93.82,96.865 93.82,98.42 94.2,98.8 94.8,98.8 95.2,99.2 95.8,99.2 R146.1@96.4,99.8
P3_ADDR_3: R148.1 X1.74 | length 5.2
  Component Side w0.15: X1.74@94.32,96.865 94.32,98.22 94.5,98.4 94.9,98.4 95.3,98.8 95.9,98.8 96.3,99.2 96.9,99.2 R148.1@97.5,99.8
P4_ADDR_0: R210.1 X8.8 | length 3.1
  Solder Side w0.15: R210.1@103.9,99.8 104.315,99.385 X8.8@104.315,96.865
P4_ADDR_1: R212.1 X8.10 | length 3.4
  Solder Side w0.15: R212.1@102.8,99.8 103.815,98.785 X8.10@103.815,96.865
P4_ADDR_2: R214.1 X8.12 | length 4
  Solder Side w0.15: R214.1@101.7,99.8 102.3,99.2 102.9,99.2 103.315,98.785 X8.12@103.315,96.865
P4_ADDR_3: R216.1 X8.14 | length 4.4
  Solder Side w0.15: R216.1@100.6,99.8 101.2,99.2 101.8,99.2 102.2,98.8 102.6,98.8 102.815,98.585 X8.14@102.815,96.865
P5_ADDR_0: R121.1 X2.8 | length 3.3
  Component Side w0.15: R121.1@128.9,99.8 129.815,98.885 X2.8@129.815,96.865
P5_ADDR_1: R123.1 X2.10 | length 3.1
  Component Side w0.15: R123.1@130,99.8 130.315,99.485 X2.10@130.315,96.865
P5_ADDR_2: R131.1 X2.12 | length 3.1
  Component Side w0.15: X2.12@130.815,96.865 130.815,99.515 R131.1@131.1,99.8
P5_ADDR_3: R125.1 X2.14 | length 3.3
  Component Side w0.15: X2.14@131.315,96.865 131.315,98.915 R125.1@132.2,99.8
P6_ADDR_0: R150.1 X3.68 | length 3.5
  Solder Side w0.15: R150.1@139.9,99.8 141.31,98.39 X3.68@141.31,96.865
P6_ADDR_1: R155.1 X3.70 | length 4.1
  Solder Side w0.15: R155.1@138.8,99.8 139.4,99.2 139.9,99.2 140.81,98.29 X3.70@140.81,96.865
P6_ADDR_2: R154.1 X3.72 | length 4.7
  Solder Side w0.15: R154.1@137.7,99.8 138.3,99.2 138.8,99.2 139.2,98.8 139.8,98.8 140.31,98.29 X3.72@140.31,96.865
P6_ADDR_3: R157.1 X3.74 | length 5.2
  Solder Side w0.15: R157.1@136.6,99.8 137.2,99.2 137.8,99.2 138.2,98.8 138.6,98.8 139,98.4 139.6,98.4 139.81,98.19 X3.74@139.81,96.865
P7_ADDR_0: R149.1 X2.68 | length 3.5
  Component Side w0.15: X2.68@149.82,96.865 149.82,98.42 R149.1@151.2,99.8
P7_ADDR_1: R156.1 X2.70 | length 4.1
  Component Side w0.15: X2.70@150.32,96.865 150.32,98.42 151.1,99.2 151.7,99.2 R156.1@152.3,99.8
P7_ADDR_2: R158.1 X2.72 | length 4.7
  Component Side w0.15: X2.72@150.82,96.865 150.82,98.42 151.2,98.8 151.8,98.8 152.2,99.2 152.8,99.2 R158.1@153.4,99.8
P7_ADDR_3: R151.1 X2.74 | length 5.2
  Component Side w0.15: X2.74@151.32,96.865 151.32,98.22 151.5,98.4 151.9,98.4 152.3,98.8 152.9,98.8 153.3,99.2 153.9,99.2 R151.1@154.5,99.8
P8_ADDR_0: R122.1 X3.8 | length 3.1
  Solder Side w0.15: R122.1@160.9,99.8 161.315,99.385 X3.8@161.315,96.865
P8_ADDR_1: R124.1 X3.10 | length 3.4
  Solder Side w0.15: R124.1@159.8,99.8 160.815,98.785 X3.10@160.815,96.865
P8_ADDR_2: R126.1 X3.12 | length 3.9
  Solder Side w0.15: R126.1@158.7,99.8 159.3,99.2 159.8,99.2 160.315,98.685 X3.12@160.315,96.865
P8_ADDR_3: R127.1 X3.14 | length 4.4
  Solder Side w0.15: R127.1@157.6,99.8 158.2,99.2 158.7,99.2 159.1,98.8 159.6,98.8 159.815,98.585 X3.14@159.815,96.865
P9_ADDR_0: R159.1 X4.8 | length 3.2
  Component Side w0.15: R159.1@186.1,99.8 186.815,99.085 X4.8@186.815,96.865
P9_ADDR_1: R188.1 X4.10 | length 3
  Component Side w0.15: R188.1@187.2,99.8 187.315,99.685 X4.10@187.315,96.865
P9_ADDR_2: R191.1 X4.12 | length 3.1
  Component Side w0.15: X4.12@187.815,96.865 187.815,99.315 R191.1@188.3,99.8
P9_ADDR_3: R194.1 X4.14 | length 3.4
  Component Side w0.15: X4.14@188.315,96.865 188.315,98.715 R194.1@189.4,99.8
P10_ADDR_0: R199.1 X5.68 | length 3.5
  Solder Side w0.15: R199.1@196.9,99.8 197.2,99.5 197.2,99.3 197.7,98.8 198.31,98.19 X5.68@198.31,96.865
P10_ADDR_1: R202.1 X5.70 | length 4
  Solder Side w0.15: R202.1@195.8,99.8 196.4,99.2 196.8,99.2 197.81,98.19 X5.70@197.81,96.865
P10_ADDR_2: R205.1 X5.72 | length 4.6
  Solder Side w0.15: R205.1@194.7,99.8 195.3,99.2 195.9,99.2 196.3,98.8 196.7,98.8 197.31,98.19 X5.72@197.31,96.865
P10_ADDR_3: R207.1 X5.74 | length 5.2
  Solder Side w0.15: R207.1@193.6,99.8 194.2,99.2 194.8,99.2 195.2,98.8 195.8,98.8 196.2,98.4 196.6,98.4 196.81,98.19 X5.74@196.81,96.865
P11_ADDR_0: R197.1 X4.68 | length 3.3
  Component Side w0.15: X4.68@206.82,96.865 206.82,98.12 208,99.3 R197.1@208,99.7
P11_ADDR_1: R204.1 X4.70 | length 4.1
  Component Side w0.15: X4.70@207.32,96.865 207.32,98.12 208.4,99.2 208.7,99.2 R204.1@209.4,99.9
P11_ADDR_2: R198.1 X4.72 | length 4.3
  Component Side w0.15: X4.72@207.82,96.865 207.82,98.12 208.5,98.8 208.8,98.8 209.2,99.2 209.8,99.2 210.2,99.6 R198.1@210.2,99.7
P11_ADDR_3: R201.1 X4.74 | length 4.9
  Component Side w0.15: X4.74@208.32,96.865 208.32,98.12 208.6,98.4 208.9,98.4 209.3,98.8 210.3,98.8 210.7,99.2 210.9,99.2 211.3,99.6 R201.1@211.3,99.7
P12_ADDR_0: R186.1 X5.8 | length 3.2
  Solder Side w0.15: R186.1@217.9,99.9 217.9,98.6 218.315,98.185 X5.8@218.315,96.865
P12_ADDR_1: R189.1 X5.10 | length 3.4
  Solder Side w0.15: R189.1@216.8,99.8 216.8,99.2 217.815,98.185 X5.10@217.815,96.865
P12_ADDR_2: R192.1 X5.12 | length 3.7
  Solder Side w0.15: R192.1@215.7,99.7 R192.1@215.7,99.8 217.315,98.185 X5.12@217.315,96.865
P12_ADDR_3: R195.1 X5.14 | length 4.2
  Solder Side w0.15: R195.1@214.6,99.8 215.3,99.1 215.9,99.1 216.815,98.185 X5.14@216.815,96.865
P13_ADDR_0: R187.1 X6.8 | length 3.3
  Component Side w0.15: R187.1@242.9,99.8 243.815,98.885 X6.8@243.815,96.865
P13_ADDR_1: R190.1 X6.10 | length 3.1
  Component Side w0.15: R190.1@244,99.8 244.315,99.485 X6.10@244.315,96.865
P13_ADDR_2: R196.1 X6.12 | length 3.1
  Component Side w0.15: X6.12@244.815,96.865 244.815,99.515 R196.1@245.1,99.8
P13_ADDR_3: R193.1 X6.14 | length 3.3
  Component Side w0.15: X6.14@245.315,96.865 245.315,98.915 R193.1@246.2,99.8
P14_ADDR_0: R217.1 X7.68 | length 3.5
  Solder Side w0.15: R217.1@253.9,99.8 255.31,98.39 X7.68@255.31,96.865
P14_ADDR_1: R221.1 X7.70 | length 4.1
  Solder Side w0.15: R221.1@252.8,99.8 253.4,99.2 254,99.2 254.81,98.39 X7.70@254.81,96.865
P14_ADDR_2: R219.1 X7.72 | length 4.7
  Solder Side w0.15: R219.1@251.7,99.8 252.3,99.2 252.8,99.2 253.2,98.8 253.9,98.8 254.31,98.39 X7.72@254.31,96.865
P14_ADDR_3: R223.1 X7.74 | length 5.2
  Solder Side w0.15: R223.1@250.6,99.8 251.2,99.2 251.7,99.2 252.1,98.8 252.6,98.8 253,98.4 253.6,98.4 253.81,98.19 X7.74@253.81,96.865
P15_ADDR_0: R200.1 X6.68 | length 3.5
  Component Side w0.15: X6.68@263.82,96.865 263.82,98.42 R200.1@265.2,99.8
P15_ADDR_1: R206.1 X6.70 | length 4
  Component Side w0.15: X6.70@264.32,96.865 264.32,98.32 265.2,99.2 265.7,99.2 R206.1@266.3,99.8
P15_ADDR_2: R208.1 X6.72 | length 4.6
  Component Side w0.15: X6.72@264.82,96.865 264.82,98.22 265.4,98.8 265.9,98.8 266.3,99.2 266.8,99.2 R208.1@267.4,99.8
P15_ADDR_3: R203.1 X6.74 | length 5.1
  Component Side w0.15: X6.74@265.32,96.865 265.32,98.12 265.6,98.4 266.1,98.4 266.5,98.8 267,98.8 267.4,99.2 267.9,99.2 R203.1@268.5,99.8
P16_ADDR_0: R209.1 X7.8 | length 3.1
  Solder Side w0.15: R209.1@274.9,99.8 275.315,99.385 X7.8@275.315,96.865
P16_ADDR_1: R211.1 X7.10 | length 3.4
  Solder Side w0.15: R211.1@273.8,99.8 274.815,98.785 X7.10@274.815,96.865
P16_ADDR_2: R213.1 X7.12 | length 3.8
  Solder Side w0.15: R213.1@272.7,99.8 273.3,99.2 273.7,99.2 274.315,98.585 X7.12@274.315,96.865
P16_ADDR_3: R215.1 X7.14 | length 4.4
  Solder Side w0.15: R215.1@271.6,99.8 272.2,99.2 272.8,99.2 273.2,98.8 273.6,98.8 273.815,98.585 X7.14@273.815,96.865
PCI_E_CLK_N: D9.AC5 X16.A14 | length 31.5
  Component Side w0.15: v4(85,55) D9.AC5@85.5,55.5
  Solder Side w0.15: v4(85,55) 85.345,54.655 86.028,54.655 86.71,53.973 86.71,52.4 87.4,51.71 87.4,48 88.71,46.69 88.71,41.59 92.6,37.7 92.6,35.9 94.155,34.345 94.155,30.92 94.5,30.575 X16.A14@94.5,28.5
PCI_E_CLK_P: D9.AD5 X16.A13 | length 31.5
  Component Side w0.15: v4@85.001,53.999 ccw(c85.285,54.215) D9.AD5@85.501,54.499
  Solder Side w0.15: v4(85,54) 85.345,54.345 85.9,54.345 86.4,53.845 86.4,52.272 87.09,51.582 87.09,47.872 88.4,46.562 88.4,41.462 92.29,37.572 92.29,35.772 93.845,34.217 93.845,30.92 93.5,30.575 X16.A13@93.5,28.5
PCI_E_RX_N: D9.AA7 X16.B15 | length 34.1
  Component Side w0.15: D9.AA7@87.5,57.5 v4(88,58) ; v8(95.4,41.6) 95.155,41.355 95.155,30.92 95.5,30.575 X16.B15@95.5,28.5
  Solder Side w0.15: v4(88,58) 88.345,57.655 89.283,57.655 90.21,56.728 90.21,55.4 90.9,54.71 90.9,51.1 92.01,49.99 92.01,46.49 95.155,43.345 95.155,41.845 v8(95.4,41.6)
PCI_E_RX_P: D9.AB7 X16.B14 | length 34.1
  Component Side w0.15: D9.AB7@87.5,56.5 87.576,56.366 ccw(c87.76,56.52) 88,56.52 v4(88,57) ; X16.B14@94.5,28.5 94.5,30.575 94.845,30.92 94.845,41.355 v8(94.6,41.6)
  Solder Side w0.15: v4(88,57) 88.345,57.345 89.155,57.345 89.9,56.6 89.9,55.272 90.59,54.582 90.59,50.972 91.7,49.862 91.7,46.362 94.845,43.217 94.845,41.845 v8(94.6,41.6)
PCI_E_TX_N: C100.1 X16.A17 | length 7.3
  Solder Side w0.15: X16.A17@97.5,28.5 97.5,30.575 97.155,30.92 97.155,35.03 C100.1@97.575,35.45
PCI_E_TX_P: C99.1 X16.A16 | length 7.3
  Solder Side w0.15: C99.1@96.425,35.45 96.845,35.03 96.845,30.92 96.5,30.575 X16.A16@96.5,28.5
PHY_1_RST#: D14.15 X1.1 | length 85.8
  Component Side w0.15: v1(68.6,92) 69.465,91.135 X1.1@71.315,91.135 ; v1(112.8,118.8) 112.8,114.325 D14.15@112.825,114.3
  Inner Layer 1 w0.15: v1(67.1,119.9) 67.1,118.9 66.4,118.2 66.4,115.1 66.7,114.8 66.7,111.9 67,111.6 68.2,111.6 68.9,110.9 68.9,107.6 68.1,106.8 68.1,106.1 68.6,105.6 68.6,99.7 69.5,98.8 69.5,92.9 v1(68.6,92)
  Inner Layer 2 w0.15: v1(67.1,119.9) 67.4,119.6 87.7,119.6 88.4,120.3 91,120.3 92.8,118.5 112.5,118.5 v1(112.8,118.8)
PHY_2_RST#: D14.1 X8.61 | length 48.3
  Component Side w0.15: v1(111.3,110.6) 111.3,109.9 111.555,109.645 D14.1@111.555,108.5
  Inner Layer 1 w0.15: v1(88.5,90.9) 88.2,91.2 88.2,92.4 89.3,93.5 89.3,108.2 90.7,109.6 90.7,110.5 v1(90,111.2)
  Inner Layer 2 w0.15: v1(90,111.2) 110.7,111.2 v1(111.3,110.6)
  Solder Side w0.15: X8.61@85.81,91.135 87.365,91.135 87.6,90.9 v1(88.5,90.9)
PHY_3_RST#: D14.2 X1.61 | length 50.1
  Component Side w0.15: v1(88.9,92) 89.765,91.135 X1.61@91.32,91.135 ; v1(112.8,110.6) 112.8,108.525 D14.2@112.825,108.5
  Inner Layer 1 w0.15: v1(88.9,92) 89.7,92.8 89.7,108 91.1,109.4 91.1,111.2 v1(90,112.3)
  Inner Layer 2 w0.15: v1(90,112.3) 90.7,111.6 111.3,111.6 112.3,110.6 v1(112.8,110.6)
PHY_4_RST#: D14.3 X8.1 | length 36.2
  Component Side w0.15: D14.3@114.095,108.5 114.1,108.505 v1(114.1,109.9)
  Inner Layer 1 w0.15: v1(104.1,88.7) 105.6,90.2 v1(105.6,110.5)
  Inner Layer 2 w0.15: v1(105.6,110.5) 110.3,110.5 110.9,109.9 v1(114.1,109.9)
  Solder Side w0.15: v1(104.1,88.7) 104.9,88.7 105.815,89.615 X8.1@105.815,91.135
PHY_5_RST#: D14.4 X2.1 | length 38.1
  Component Side w0.15: D14.4@115.365,108.5 115.4,108.535 v1(115.4,109.9) ; X2.1@128.315,91.135 128.315,89.585 128.7,89.2 v1(129.5,89.2)
  Inner Layer 1 w0.15: v1(128.6,109.1) 128.6,90.1 v1(129.5,89.2)
  Inner Layer 2 w0.15: v1(115.4,109.9) 116.2,109.1 v1(128.6,109.1)
PHY_6_RST#: D14.5 X3.61 | length 48.4
  Component Side w0.15: D14.5@116.635,108.5 116.7,108.435 v1(116.7,106.1)
  Inner Layer 1 w0.15: v1(144.3,91.8) 146,93.5 146,105.1 v1(145.7,105.4)
  Inner Layer 2 w0.15: v1(116.7,106.1) 117.4,105.4 118.3,105.4 118.9,106 145.1,106 v1(145.7,105.4)
  Solder Side w0.15: X3.61@142.81,91.135 143.635,91.135 v1(144.3,91.8)
PHY_7_RST#: D14.6 X2.61 | length 47.9
  Component Side w0.15: v1(117.9,106.1) 117.905,106.105 D14.6@117.905,108.5 ; v1(146.8,91.8) 147.465,91.135 X2.61@148.32,91.135
  Inner Layer 1 w0.15: v1(146.8,91.8) 146.5,92.1 146.5,105.8 v1(146.8,106.1)
  Inner Layer 2 w0.15: v1(117.9,106.1) 118.2,106.4 145.9,106.4 146.2,106.1 v1(146.8,106.1)
PHY_8_RST#: D14.7 X3.1 | length 64.1
  Component Side w0.15: D14.7@119.175,108.5 119.2,108.525 v1(119.2,109.9)
  Inner Layer 1 w0.15: v1@163,107.6 163,100.7 164.2,99.5 v1(164.2,91.8)
  Inner Layer 2 w0.15: v1(119.2,109.9) 136.8,109.9 138.9,107.8 162.3,107.8 162.5,108 v1(163,108)
  Solder Side w0.15: X3.1@162.815,91.135 163.535,91.135 v1(164.2,91.8)
PHY_9_RST#: D15.15 X4.1 | length 76.8
  Component Side w0.15: v1(181.2,91.1) 185.28,91.1 X4.1@185.315,91.135
  Inner Layer 1 w0.15: v1(181.2,91.1) v1(181.2,105)
  Inner Layer 2 w0.15: v1(181.2,105) 200,105 203,108 205.6,108 206.2,107.4 230.5,107.4 v1(233.2,110.1)
  Solder Side w0.15: D15.15@233.175,114.3 233.2,114.275 v1(233.2,110.1)
PHY_10_RST#: D15.7 X5.61 | length 43.2
  Inner Layer 1 w0.15: v1(199.9,93) 202.5,95.6 v1(202.5,106.4)
  Inner Layer 2 w0.15: v1(202.5,106.4) 226.5,106.4 v1(226.8,106.1)
  Solder Side w0.15: X5.61@199.81,91.135 199.81,92.91 v1(199.9,93) ; v1(226.8,106.1) 226.825,106.125 D15.7@226.825,108.5
PHY_11_RST#: D15.6 X4.61 | length 53.4
  Component Side w0.15: v1(205.2,86.9) 205.32,87.02 X4.61@205.32,91.135
  Inner Layer 1 w0.15: v1(203.3,105.6) 202.9,105.2 202.9,89.2 v1(205.2,86.9)
  Inner Layer 2 w0.15: v1(203.3,105.6) 203.7,106 218,106 219,105 219.6,105 220.2,105.6 225.5,105.6 226.1,105 227.5,105 227.8,105.3 v1(228.2,105.3)
  Solder Side w0.15: D15.6@228.095,108.5 228.2,108.395 v1(228.2,105.3)
PHY_12_RST#: D15.5 X5.1 | length 33.8
  Inner Layer 1 w0.15: v1(218.3,88.8) 219.3,89.8 v1(219.3,105.7)
  Inner Layer 2 w0.15: v1(219.3,105.7) 219.6,106 225.8,106 226.4,105.4 227.2,105.4 227.9,106.1 v1(229.5,106.1)
  Solder Side w0.15: v1(218.3,88.8) 218.7,88.8 219.815,89.915 X5.1@219.815,91.135 ; D15.5@229.365,108.5 229.5,108.365 v1(229.5,106.1)
PHY_13_RST#: D15.4 X6.1 | length 26.6
  Component Side w0.15: v1(236.2,90.9) 242.315,90.9 X6.1@242.315,91.135
  Inner Layer 1 w0.15: v1(230.7,106.1) 231.5,105.3 231.5,97.9 236.6,92.8 236.6,91.3 v1(236.2,90.9)
  Solder Side w0.15: D15.4@230.635,108.5 230.7,108.435 v1(230.7,106.1)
